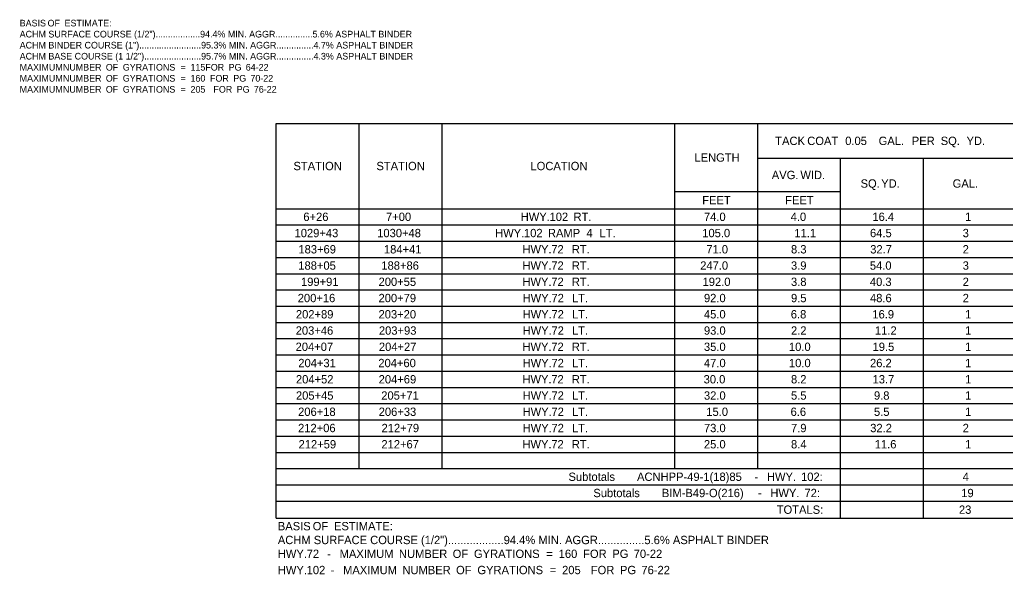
# Model space of a CAD drawing. Extents: x 1226567 to 1228151, y 151309 to 152305.
# Drawn here: x 1226568 to 1227158, y 151330 to 151663 of the extents above; entities that cross this region are included whole.
import ezdxf

# ---------------------------------------------------------------- set-up
doc = ezdxf.new("R2010")
doc.units = 0
doc.layers.add('R_Dimension', color=7, linetype='Continuous')

msp = doc.modelspace()

# ---------------------------------------------------------------- linework, layer by layer
at = {"layer": 'R_Dimension'}
for p, q in [((1226721.38, 151600.64), (1227956.7, 151600.64)), ((1226721.38, 151363.71), (1226721.38, 151600.64)), ((1226771.1, 151393.45), (1226771.1, 151600.64)), ((1226820.83, 151393.45), (1226820.83, 151600.64)), ((1226960.25, 151393.45), (1226960.25, 151600.64)), ((1227009.98, 151393.45), (1227009.98, 151600.64)), ((1227009.98, 151579.68), (1227956.7, 151579.68)), ((1227059.7, 151363.71), (1227059.7, 151579.68)), ((1227109.43, 151363.71), (1227109.43, 151579.68)), ((1226960.25, 151559.69), (1227059.7, 151559.69)), ((1226721.38, 151549.45), (1227757.8, 151549.45)), ((1227059.7, 151549.45), (1227208.88, 151549.45)), ((1226721.38, 151539.7), (1227956.7, 151539.7)), ((1226721.38, 151529.95), (1227956.7, 151529.95)), ((1226721.38, 151520.2), (1227956.7, 151520.2)), ((1226721.38, 151510.45), (1227956.7, 151510.45)), ((1226721.38, 151500.7), (1227956.7, 151500.7)), ((1226721.38, 151490.95), (1227956.7, 151490.95)), ((1226721.38, 151481.2), (1227956.7, 151481.2)), ((1226721.38, 151471.45), (1227956.7, 151471.45)), ((1226721.38, 151461.7), (1227956.7, 151461.7)), ((1226721.38, 151451.95), (1227956.7, 151451.95)), ((1226721.38, 151442.2), (1227956.7, 151442.2)), ((1226721.38, 151432.45), (1227956.7, 151432.45)), ((1226721.38, 151422.7), (1227956.7, 151422.7)), ((1226721.38, 151412.95), (1227956.7, 151412.95)), ((1226721.38, 151403.2), (1227956.7, 151403.2)), ((1226721.38, 151393.45), (1227956.7, 151393.45)), ((1226721.38, 151383.7), (1227956.7, 151383.7)), ((1226721.38, 151373.95), (1227956.7, 151373.95)), ((1226721.38, 151363.71), (1227956.7, 151363.71))]:
    msp.add_line(p, q, dxfattribs=at)

# ---------------------------------------------------------------- texts
for s, height, p in [('BASIS', 3.994, (1226567.62, 151658.82)), (' OF', 3.994, (1226582.85, 151658.82)), (' ESTIMATE:', 3.994, (1226593.04, 151658.82)), ('ACHM SURFACE COURSE (1/2")..................94.4% MIN. AGGR...............5.6% ASPHALT BINDER', 3.9945, (1226567.62, 151652.2)), ('ACHM BINDER COURSE (1").........................95.3% MIN. AGGR...............4.7% ASPHALT BINDER', 3.9945, (1226567.62, 151645.58)), ('ACHM BASE COURSE (1 1/2").......................95.7% MIN. AGGR...............4.3% ASPHALT BINDER', 3.9945, (1226567.62, 151638.96)), ('MAXIMUM', 3.994, (1226567.62, 151632.33)), (' NUMBER', 3.994, (1226592.03, 151632.33)), (' OF', 3.994, (1226617.76, 151632.33)), (' GYRATIONS', 3.994, (1226627.95, 151632.33)), (' =', 3.994, (1226662.58, 151632.33)), (' 115', 3.994, (1226668.52, 151632.33)), (' FOR', 3.994, (1226677.42, 151632.33)), (' PG', 3.994, (1226691.39, 151632.33)), (' 64-22', 3.994, (1226701.64, 151632.33)), ('MAXIMUM', 3.994, (1226567.62, 151625.71)), (' NUMBER', 3.994, (1226592.03, 151625.71)), (' OF', 3.994, (1226617.76, 151625.71)), (' GYRATIONS', 3.994, (1226627.95, 151625.71)), (' =', 3.994, (1226662.58, 151625.71)), (' 160', 3.994, (1226668.52, 151625.71)), (' FOR', 3.994, (1226680.22, 151625.71)), (' PG', 3.994, (1226694.19, 151625.71)), (' 70-22', 3.994, (1226704.44, 151625.71)), ('MAXIMUM', 3.994, (1226567.62, 151619.09)), (' NUMBER', 3.994, (1226592.03, 151619.09)), (' OF', 3.994, (1226617.76, 151619.09)), (' GYRATIONS', 3.994, (1226627.95, 151619.09)), (' =', 3.994, (1226662.58, 151619.09)), (' 205', 3.994, (1226668.52, 151619.09)), (' FOR', 3.994, (1226682.27, 151619.09)), (' PG', 3.994, (1226696.23, 151619.09)), (' 76-22', 3.994, (1226706.49, 151619.09)), ('TACK', 5, (1227020.51, 151587.66)), (' COAT', 5, (1227037.83, 151587.66)), (' 0.05', 5, (1227060.59, 151587.66)), (' GAL.', 5, (1227080.63, 151587.66)), (' PER', 5, (1227100.51, 151587.66)), (' SQ.', 5, (1227117.83, 151587.66)), (' YD.', 5, (1227133.31, 151587.66)), ('LENGTH', 5, (1226972.05, 151577.66)), ('STATION', 5, (1226731.73, 151572.55)), ('STATION', 5, (1226781.46, 151572.55)), ('LOCATION', 5, (1226873.79, 151572.55)), ('AVG.', 5, (1227018.44, 151567.18)), (' WID.', 5, (1227033.72, 151567.18)), ('SQ.', 5, (1227071.67, 151562.06)), (' YD.', 5, (1227082.15, 151562.06)), ('GAL.', 5, (1227126.85, 151562.06)), ('FEET', 5, (1226976.75, 151552.07)), ('FEET', 5, (1227026.48, 151552.07)), ('6+26', 5, (1226737.64, 151542.08)), ('7+00', 5, (1226787.21, 151542.08)), ('HWY.', 5, (1226867.94, 151542.08)), (' 102', 5, (1226883.38, 151542.08)), (' RT.', 5, (1226897.75, 151542.08)), ('74.0', 5, (1226977.77, 151542.08)), ('4.0', 5, (1227029.74, 151542.08)), ('16.4', 5, (1227078.74, 151542.08)), ('1', 5, (1227134.29, 151542.08)), ('1029+43', 5, (1226732.38, 151532.33)), ('1030+48', 5, (1226781.91, 151532.33)), ('HWY.', 5, (1226852.61, 151532.33)), (' 102', 5, (1226868.04, 151532.33)), (' RAMP', 5, (1226882.41, 151532.33)), (' 4', 5, (1226905.48, 151532.33)), (' LT.', 5, (1226913.32, 151532.33)), ('105.0', 5, (1226976.75, 151532.33)), ('11.1', 5, (1227031.97, 151532.33)), ('64.5', 5, (1227077.32, 151532.33)), ('3', 5, (1227132.87, 151532.33)), ('183+69', 5, (1226734.69, 151522.58)), ('184+41', 5, (1226785.97, 151522.58)), ('HWY.', 5, (1226868.97, 151522.58)), (' 72', 5, (1226884.4, 151522.58)), (' RT.', 5, (1226896.72, 151522.58)), ('71.0', 5, (1226979.19, 151522.58)), ('8.3', 5, (1227029.96, 151522.58)), ('32.7', 5, (1227077.44, 151522.58)), ('2', 5, (1227132.87, 151522.58)), ('188+05', 5, (1226734.63, 151512.83)), ('188+86', 5, (1226784.41, 151512.83)), ('HWY.', 5, (1226868.97, 151512.83)), (' 72', 5, (1226884.4, 151512.83)), (' RT.', 5, (1226896.72, 151512.83)), ('247.0', 5, (1226975.53, 151512.83)), ('3.9', 5, (1227029.94, 151512.83)), ('54.0', 5, (1227077.22, 151512.83)), ('3', 5, (1227132.87, 151512.83)), ('199+91', 5, (1226736.24, 151503.08)), ('200+55', 5, (1226782.74, 151503.08)), ('HWY.', 5, (1226868.97, 151503.08)), (' 72', 5, (1226884.4, 151503.08)), (' RT.', 5, (1226896.72, 151503.08)), ('192.0', 5, (1226976.95, 151503.08)), ('3.8', 5, (1227029.96, 151503.08)), ('40.3', 5, (1227077.24, 151503.08)), ('2', 5, (1227132.87, 151503.08)), ('200+16', 5, (1226734.29, 151493.33)), ('200+79', 5, (1226782.72, 151493.33)), ('HWY.', 5, (1226869.08, 151493.33)), (' 72', 5, (1226884.52, 151493.33)), (' LT.', 5, (1226896.84, 151493.33)), ('92.0', 5, (1226977.77, 151493.33)), ('9.5', 5, (1227029.96, 151493.33)), ('48.6', 5, (1227077.3, 151493.33)), ('2', 5, (1227132.87, 151493.33)), ('202+89', 5, (1226733.19, 151483.58)), ('203+20', 5, (1226782.72, 151483.58)), ('HWY.', 5, (1226869.08, 151483.58)), (' 72', 5, (1226884.52, 151483.58)), (' LT.', 5, (1226896.84, 151483.58)), ('45.0', 5, (1226977.77, 151483.58)), ('6.8', 5, (1227029.84, 151483.58)), ('16.9', 5, (1227078.72, 151483.58)), ('1', 5, (1227134.29, 151483.58)), ('203+46', 5, (1226733.07, 151473.83)), ('203+93', 5, (1226782.93, 151473.83)), ('HWY.', 5, (1226869.08, 151473.83)), (' 72', 5, (1226884.52, 151473.83)), (' LT.', 5, (1226896.84, 151473.83)), ('93.0', 5, (1226977.77, 151473.83)), ('2.2', 5, (1227029.96, 151473.83)), ('11.2', 5, (1227080.27, 151473.83)), ('1', 5, (1227134.29, 151473.83)), ('204+07', 5, (1226733.01, 151464.08)), ('204+27', 5, (1226782.93, 151464.08)), ('HWY.', 5, (1226868.97, 151464.08)), (' 72', 5, (1226884.4, 151464.08)), (' RT.', 5, (1226896.72, 151464.08)), ('35.0', 5, (1226977.77, 151464.08)), ('10.0', 5, (1227028.72, 151464.08)), ('19.5', 5, (1227078.86, 151464.08)), ('1', 5, (1227134.29, 151464.08)), ('204+31', 5, (1226734.63, 151454.33)), ('204+60', 5, (1226782.6, 151454.33)), ('HWY.', 5, (1226869.08, 151454.33)), (' 72', 5, (1226884.52, 151454.33)), (' LT.', 5, (1226896.84, 151454.33)), ('47.0', 5, (1226977.77, 151454.33)), ('10.0', 5, (1227028.72, 151454.33)), ('26.2', 5, (1227077.32, 151454.33)), ('1', 5, (1227134.29, 151454.33)), ('204+52', 5, (1226733.21, 151444.58)), ('204+69', 5, (1226782.8, 151444.58)), ('HWY.', 5, (1226868.97, 151444.58)), (' 72', 5, (1226884.4, 151444.58)), (' RT.', 5, (1226896.72, 151444.58)), ('30.0', 5, (1226977.58, 151444.58)), ('8.2', 5, (1227029.96, 151444.58)), ('13.7', 5, (1227078.86, 151444.58)), ('1', 5, (1227134.29, 151444.58)), ('205+45', 5, (1226733.21, 151434.83)), ('205+71', 5, (1226784.35, 151434.83)), ('HWY.', 5, (1226869.08, 151434.83)), (' 72', 5, (1226884.52, 151434.83)), (' LT.', 5, (1226896.84, 151434.83)), ('32.0', 5, (1226977.77, 151434.83)), ('5.5', 5, (1227029.96, 151434.83)), ('9.8', 5, (1227079.68, 151434.83)), ('1', 5, (1227134.29, 151434.83)), ('206+18', 5, (1226734.51, 151425.08)), ('206+33', 5, (1226782.82, 151425.08)), ('HWY.', 5, (1226869.08, 151425.08)), (' 72', 5, (1226884.52, 151425.08)), (' LT.', 5, (1226896.84, 151425.08)), ('15.0', 5, (1226979.19, 151425.08)), ('6.6', 5, (1227029.7, 151425.08)), ('5.5', 5, (1227079.68, 151425.08)), ('1', 5, (1227134.29, 151425.08)), ('212+06', 5, (1226734.49, 151415.33)), ('212+79', 5, (1226784.53, 151415.33)), ('HWY.', 5, (1226869.08, 151415.33)), (' 72', 5, (1226884.52, 151415.33)), (' LT.', 5, (1226896.84, 151415.33)), ('73.0', 5, (1226977.77, 151415.33)), ('7.9', 5, (1227029.94, 151415.33)), ('32.2', 5, (1227077.44, 151415.33)), ('2', 5, (1227132.87, 151415.33)), ('212+59', 5, (1226734.8, 151405.58)), ('212+67', 5, (1226784.43, 151405.58)), ('HWY.', 5, (1226868.97, 151405.58)), (' 72', 5, (1226884.4, 151405.58)), (' RT.', 5, (1226896.72, 151405.58)), ('25.0', 5, (1226977.77, 151405.58)), ('8.4', 5, (1227029.96, 151405.58)), ('11.6', 5, (1227080.14, 151405.58)), ('1', 5, (1227134.29, 151405.58)), ('Subtotals', 5, (1226896.6, 151386.08)), (' ACNHPP-49-1(18)85', 5, (1226935.81, 151386.08)), (' -', 5, (1227006.24, 151386.08)), (' HWY.', 5, (1227013.68, 151386.08)), (' 102:', 5, (1227034.12, 151386.08)), ('4', 5, (1227132.87, 151386.08)), ('Subtotals', 5, (1226911.48, 151376.33)), (' BIM-B49-O(216)', 5, (1226950.69, 151376.33)), (' HWY.', 5, (1227015.73, 151376.33)), (' 72:', 5, (1227036.17, 151376.33)), ('19', 5, (1227132.03, 151376.33)), (' -', 5, (1227008.29, 151376.33)), ('TOTALS:', 5, (1227021.4, 151366.33)), ('23', 5, (1227130.63, 151366.33)), ('BASIS', 5, (1226722.35, 151356.43)), (' OF', 5, (1226741.41, 151356.43)), (' ESTIMATE:', 5, (1226754.16, 151356.43)), ('ACHM SURFACE COURSE (1/2")..................94.4% MIN. AGGR...............5.6% ASPHALT BINDER', 5, (1226722.35, 151348.14)), ('HWY.', 5, (1226722.35, 151339.85)), (' 72', 5, (1226737.79, 151339.85)), (' MAXIMUM', 5, (1226757.55, 151339.85)), (' NUMBER', 5, (1226793.1, 151339.85)), (' OF', 5, (1226825.31, 151339.85)), (' GYRATIONS', 5, (1226838.06, 151339.85)), (' 160', 5, (1226888.85, 151339.85)), (' FOR', 5, (1226903.5, 151339.85)), (' PG', 5, (1226920.98, 151339.85)), (' 70-22', 5, (1226933.81, 151339.85)), (' -', 5, (1226750.11, 151339.85)), (' =', 5, (1226881.41, 151339.85)), ('HWY.', 5, (1226722.35, 151330.1)), (' 102', 5, (1226737.79, 151330.1)), (' -', 5, (1226752.16, 151330.1)), (' MAXIMUM', 5, (1226759.6, 151330.1)), (' NUMBER', 5, (1226795.15, 151330.1)), (' OF', 5, (1226827.35, 151330.1)), (' GYRATIONS', 5, (1226840.11, 151330.1)), (' =', 5, (1226883.46, 151330.1)), (' 205', 5, (1226890.9, 151330.1)), (' FOR', 5, (1226908.1, 151330.1)), (' PG', 5, (1226925.58, 151330.1)), (' 76-22', 5, (1226938.42, 151330.1))]:
    msp.add_text(s, height=height, dxfattribs=at).set_placement(p)

doc.saveas('drawing.dxf')
